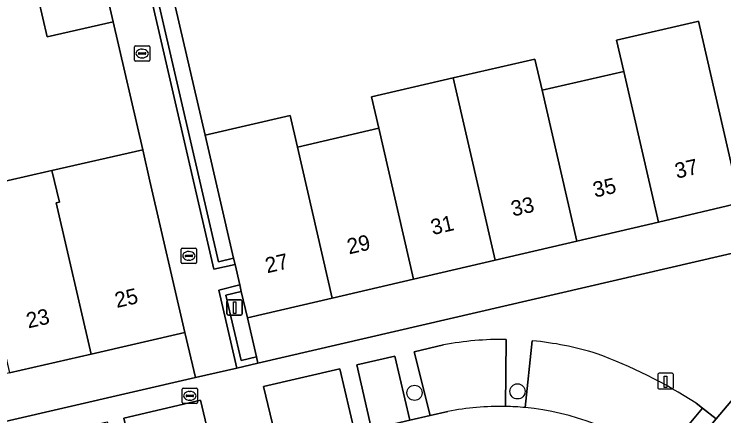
# Model space of a CAD drawing. Extents: x 156412 to 157779, y 382335 to 383768.
# Drawn here: x 156818.92 to 156864.72, y 382584.85 to 382610.78 of the extents above; entities that cross this region are included whole.
import ezdxf

# ---------------------------------------------------------------- set-up
doc = ezdxf.new("R2010")
doc.units = 0
for name, color, linetype in [('IMGEO_Boom', 7, 'Continuous'), ('IMGEO_Brandkraan', 7, 'Continuous'), ('IMGEO_Erf', 7, 'Continuous'), ('IMGEO_Groenvoorziening', 7, 'Continuous'), ('IMGEO_Kolk', 7, 'Continuous'), ('IMGEO_Laadpaal', 7, 'Continuous'), ('IMGEO_Lichtmast', 7, 'Continuous'), ('IMGEO_Muur', 7, 'Continuous'), ('IMGEO_Pand', 7, 'Continuous'), ('IMGEO_Pand_nummerreeks', 7, 'Continuous'), ('IMGEO_Parkeervlak_open', 7, 'Continuous'), ('IMGEO_Rijbaan_lokaal_open', 7, 'Continuous'), ('IMGEO_Voetpad_open', 7, 'Continuous')]:
    doc.layers.add(name, color=color, linetype=linetype)

msp = doc.modelspace()

# ---------------------------------------------------------------- linework, layer by layer
at = {"layer": 'IMGEO_Boom'}
for centre in [(156844.759, 382586.335), (156851.401, 382586.427)]:
    msp.add_circle(centre, 0.489, dxfattribs=at)
at = {"layer": 'IMGEO_Brandkraan'}
for p, q in [((156829.756, 382585.715), (156829.756, 382586.567)), ((156829.831, 382586.641), (156830.683, 382586.641)), ((156830.757, 382586.567), (156830.757, 382585.715)), ((156830.015, 382586.135), (156830.015, 382586.147)), ((156830.453, 382586.098), (156830.055, 382586.098)), ((156830.058, 382586.184), (156830.456, 382586.184)), ((156830.244, 382586.421), (156830.269, 382586.421)), ((156830.499, 382586.147), (156830.499, 382586.135)), ((156830.683, 382585.641), (156829.831, 382585.641)), ((156830.267, 382585.861), (156830.242, 382585.861))]:
    msp.add_line(p, q, dxfattribs=at)
for points in [[(156829.756, 382585.715), (156829.756, 382586.567)], [(156829.831, 382586.641), (156830.683, 382586.641)], [(156830.757, 382586.567), (156830.757, 382585.715)], [(156830.683, 382585.641), (156829.831, 382585.641)]]:
    msp.add_lwpolyline(points, dxfattribs=at)
for centre, radius, start, end in [((156829.833, 382586.565), 0.0765, 91.552, 178.448), ((156829.833, 382586.565), 0.0765, 91.552, 178.448), ((156830.681, 382586.565), 0.0765, 1.552, 88.448), ((156830.681, 382586.565), 0.0765, 1.552, 88.448), ((156830.055, 382586.144), 0.0403, 85.8775, 175.7526), ((156830.052, 382586.134), 0.0366, 178.938, 274.7102), ((156830.456, 382586.141), 0.043, 264.8664, 352.4533), ((156830.46, 382586.146), 0.0386, 1.7309, 96.639), ((156829.833, 382585.717), 0.0765, 181.552, 268.448), ((156829.833, 382585.717), 0.0765, 181.552, 268.448), ((156830.681, 382585.717), 0.0765, 271.552, 358.448), ((156830.681, 382585.717), 0.0765, 271.552, 358.448)]:
    msp.add_arc(centre, radius, start, end, dxfattribs=at)
for centre, major_axis, ratio, start_param, end_param in [((156830.243, 382586.141), (-0.387, 0.002), 0.722429, 4.712389, 7.853982), ((156830.268, 382586.141), (-0.39, 0.002), 0.717154, 1.570796, 4.712389)]:
    msp.add_ellipse(centre, major_axis=major_axis, ratio=ratio, start_param=start_param, end_param=end_param, dxfattribs=at)
at = {"layer": 'IMGEO_Erf'}
for points in [[(156777.894, 382590.654), (156783.154, 382591.87), (156788.417, 382593.085), (156794.262, 382594.436), (156800.108, 382595.787), (156805.37, 382597.003), (156810.631, 382598.218), (156815.892, 382599.434), (156821.154, 382600.649), (156821.36, 382600.697), (156827.213, 382602.013), (156825.3, 382610.293), (156821.059, 382609.319), (156820.499, 382611.756)], [(156829.34, 382611.218), (156831.242, 382602.959), (156836.734, 382604.23), (156837.2, 382602.203), (156842.451, 382603.42), (156841.986, 382605.445), (156847.247, 382606.663), (156852.527, 382607.885), (156852.992, 382605.864), (156858.262, 382607.085), (156857.798, 382609.104), (156863.022, 382610.313), (156863.078, 382610.326), (156865.776, 382598.593), (156860.497, 382597.361), (156855.229, 382596.131), (156849.951, 382594.899), (156844.692, 382593.671), (156839.443, 382592.446), (156833.97, 382591.169), (156834.559, 382588.649), (156834.65, 382588.258), (156868.154, 382596.018)]]:
    msp.add_lwpolyline(points, dxfattribs=at)
msp.add_lwpolyline([(156830.614, 382587.326), (156829.943, 382590.238), (156823.882, 382588.838), (156818.621, 382587.623), (156813.403, 382586.418), (156808.098, 382585.193), (156802.836, 382583.978), (156796.99, 382582.627), (156791.144, 382581.277), (156785.883, 382580.062), (156780.621, 382578.847), (156775.36, 382577.632), (156770.098, 382576.416), (156764.837, 382575.201), (156759.384, 382573.942), (156760.061, 382571.022)], close=True, dxfattribs=at)
at = {"layer": 'IMGEO_Groenvoorziening'}
for points in [[(156829.34, 382611.218), (156828.87, 382613.267), (156827.892, 382613.043), (156832.104, 382594.787), (156833.079, 382595.021), (156831.242, 382602.959)], [(156833.561, 382588.417), (156834.559, 382588.649), (156833.97, 382591.169), (156833.573, 382592.883), (156832.585, 382592.65)]]:
    msp.add_lwpolyline(points, close=True, dxfattribs=at)
at = {"layer": 'IMGEO_Kolk'}
for p, q in [((156826.678, 382607.815), (156826.678, 382608.667)), ((156826.753, 382608.741), (156827.605, 382608.741)), ((156827.679, 382608.667), (156827.679, 382607.815)), ((156826.937, 382608.235), (156826.937, 382608.247)), ((156827.375, 382608.198), (156826.977, 382608.198)), ((156826.98, 382608.284), (156827.378, 382608.284)), ((156827.166, 382608.521), (156827.191, 382608.521)), ((156827.421, 382608.247), (156827.421, 382608.235)), ((156827.605, 382607.741), (156826.753, 382607.741)), ((156827.189, 382607.961), (156827.164, 382607.961)), ((156829.694, 382594.752), (156829.694, 382595.604)), ((156829.769, 382595.678), (156830.621, 382595.678)), ((156830.182, 382595.458), (156830.207, 382595.458)), ((156830.695, 382595.604), (156830.695, 382594.752)), ((156829.953, 382595.172), (156829.953, 382595.184)), ((156830.391, 382595.135), (156829.993, 382595.135)), ((156829.996, 382595.221), (156830.394, 382595.221)), ((156830.205, 382594.898), (156830.18, 382594.898)), ((156830.437, 382595.184), (156830.437, 382595.172)), ((156830.621, 382594.678), (156829.769, 382594.678))]:
    msp.add_line(p, q, dxfattribs=at)
for points in [[(156826.678, 382607.815), (156826.678, 382608.667)], [(156826.753, 382608.741), (156827.605, 382608.741)], [(156827.679, 382608.667), (156827.679, 382607.815)], [(156827.605, 382607.741), (156826.753, 382607.741)], [(156829.694, 382594.752), (156829.694, 382595.604)], [(156829.769, 382595.678), (156830.621, 382595.678)], [(156830.695, 382595.604), (156830.695, 382594.752)], [(156830.621, 382594.678), (156829.769, 382594.678)]]:
    msp.add_lwpolyline(points, dxfattribs=at)
for centre, radius, start, end in [((156826.755, 382608.665), 0.0765, 91.552, 178.448), ((156826.755, 382608.665), 0.0765, 91.552, 178.448), ((156827.603, 382608.665), 0.0765, 1.552, 88.448), ((156827.603, 382608.665), 0.0765, 1.552, 88.448), ((156826.977, 382608.244), 0.0403, 85.8775, 175.7526), ((156826.974, 382608.234), 0.0366, 178.938, 274.7102), ((156827.378, 382608.241), 0.043, 264.8664, 352.4533), ((156827.382, 382608.246), 0.0386, 1.7309, 96.639), ((156826.755, 382607.817), 0.0765, 181.552, 268.448), ((156826.755, 382607.817), 0.0765, 181.552, 268.448), ((156827.603, 382607.817), 0.0765, 271.552, 358.448), ((156827.603, 382607.817), 0.0765, 271.552, 358.448), ((156829.771, 382595.602), 0.0765, 91.552, 178.448), ((156829.771, 382595.602), 0.0765, 91.552, 178.448), ((156830.619, 382595.602), 0.0765, 1.552, 88.448), ((156830.619, 382595.602), 0.0765, 1.552, 88.448), ((156829.993, 382595.181), 0.0403, 85.8775, 175.7526), ((156829.99, 382595.171), 0.0366, 178.938, 274.7102), ((156830.394, 382595.178), 0.043, 264.8664, 352.4533), ((156830.398, 382595.183), 0.0386, 1.7309, 96.639), ((156829.771, 382594.754), 0.0765, 181.552, 268.448), ((156829.771, 382594.754), 0.0765, 181.552, 268.448), ((156830.619, 382594.754), 0.0765, 271.552, 358.448), ((156830.619, 382594.754), 0.0765, 271.552, 358.448)]:
    msp.add_arc(centre, radius, start, end, dxfattribs=at)
for centre, major_axis, ratio, start_param, end_param in [((156827.165, 382608.241), (-0.387, 0.002), 0.722429, 4.712389, 7.853982), ((156827.19, 382608.241), (-0.39, 0.002), 0.717154, 1.570796, 4.712389), ((156830.181, 382595.178), (-0.387, 0.002), 0.722429, 4.712389, 7.853982), ((156830.206, 382595.178), (-0.39, 0.002), 0.717154, 1.570796, 4.712389)]:
    msp.add_ellipse(centre, major_axis=major_axis, ratio=ratio, start_param=start_param, end_param=end_param, dxfattribs=at)
at = {"layer": 'IMGEO_Laadpaal'}
for p, q in [((156860.461, 382587.51), (156860.461, 382586.669)), ((156860.461, 382587.51), (156860.461, 382586.669)), ((156861.377, 382587.594), (156860.536, 382587.594)), ((156861.377, 382587.594), (156860.536, 382587.594)), ((156861.461, 382586.678), (156861.461, 382587.519)), ((156861.461, 382586.678), (156861.461, 382587.519)), ((156860.545, 382586.594), (156861.386, 382586.594)), ((156860.545, 382586.594), (156861.386, 382586.594))]:
    msp.add_line(p, q, dxfattribs=at)
msp.add_lwpolyline([(156860.876, 382587.407), (156861.036, 382587.407), (156861.036, 382586.674), (156860.876, 382586.674), (156860.876, 382587.407)], dxfattribs=at)
for centre, start, end in [((156860.539, 382587.516), 92.4484, 184.2845), ((156860.539, 382587.516), 92.4484, 184.2845), ((156861.383, 382587.516), 2.4484, 94.2845), ((156861.383, 382587.516), 2.4484, 94.2845), ((156860.539, 382586.672), 182.4484, 274.2845), ((156860.539, 382586.672), 182.4484, 274.2845), ((156861.383, 382586.672), 272.4484, 4.2845), ((156861.383, 382586.672), 272.4484, 4.2845)]:
    msp.add_arc(centre, 0.0779, start, end, dxfattribs=at)
at = {"layer": 'IMGEO_Lichtmast'}
for p, q in [((156832.651, 382591.438), (156832.651, 382592.238)), ((156832.651, 382592.238), (156832.651, 382591.438)), ((156832.751, 382592.338), (156833.541, 382592.338)), ((156833.541, 382592.338), (156832.751, 382592.338)), ((156833.641, 382592.238), (156833.641, 382591.438)), ((156833.641, 382591.438), (156833.641, 382592.238)), ((156833.541, 382591.338), (156832.751, 382591.338)), ((156832.751, 382591.338), (156833.541, 382591.338))]:
    msp.add_line(p, q, dxfattribs=at)
msp.add_lwpolyline([(156833.071, 382592.213), (156833.221, 382592.213), (156833.221, 382591.463), (156833.071, 382591.463), (156833.071, 382592.213)], dxfattribs=at)
for centre, start, end in [((156832.751, 382592.238), 90, 180), ((156832.751, 382592.238), 90, 180), ((156833.541, 382592.238), 0, 90), ((156833.541, 382592.238), 360, 90), ((156832.751, 382591.438), 180, 270), ((156832.751, 382591.438), 180, 270), ((156833.541, 382591.438), 270, 0), ((156833.541, 382591.438), 270, 0)]:
    msp.add_arc(centre, 0.1, start, end, dxfattribs=at)
at = {"layer": 'IMGEO_Muur'}
for points in [[(156827.892, 382613.043), (156828.87, 382613.267), (156828.778, 382613.665), (156827.414, 382613.34), (156831.805, 382594.319), (156833.171, 382594.621), (156833.079, 382595.021), (156832.104, 382594.787)], [(156832.585, 382592.65), (156833.573, 382592.883), (156833.478, 382593.297), (156832.121, 382592.971), (156833.281, 382587.934), (156834.65, 382588.258), (156834.559, 382588.649), (156833.561, 382588.417)]]:
    msp.add_lwpolyline(points, close=True, dxfattribs=at)
for points in [[(156831.242, 382602.959), (156829.34, 382611.218)], [(156825.3, 382610.293), (156827.681, 382599.996)]]:
    msp.add_lwpolyline(points, dxfattribs=at)
at = {"layer": 'IMGEO_Pand'}
for points in [[(156824.748, 382612.732), (156820.499, 382611.756), (156821.059, 382609.319), (156825.3, 382610.293)], [(156863.078, 382610.326), (156863.022, 382610.313), (156857.798, 382609.104), (156858.262, 382607.085), (156860.497, 382597.361), (156865.776, 382598.593)], [(156852.992, 382605.864), (156852.527, 382607.885), (156847.247, 382606.663), (156849.951, 382594.899), (156855.229, 382596.131)], [(156858.262, 382607.085), (156852.992, 382605.864), (156855.229, 382596.131), (156860.497, 382597.361)], [(156847.247, 382606.663), (156841.986, 382605.445), (156842.451, 382603.42), (156844.692, 382593.671), (156849.951, 382594.899)], [(156837.2, 382602.203), (156836.734, 382604.23), (156831.242, 382602.959), (156833.079, 382595.021), (156833.171, 382594.621), (156833.478, 382593.297), (156833.573, 382592.883), (156833.97, 382591.169), (156839.443, 382592.446)], [(156842.451, 382603.42), (156837.2, 382602.203), (156839.443, 382592.446), (156844.692, 382593.671)], [(156827.681, 382599.996), (156827.213, 382602.013), (156821.36, 382600.697), (156821.836, 382598.641), (156821.629, 382598.593), (156823.882, 382588.838), (156829.943, 382590.238)], [(156815.892, 382599.434), (156818.621, 382587.623), (156823.882, 382588.838), (156821.629, 382598.593), (156821.836, 382598.641), (156821.36, 382600.697), (156821.154, 382600.649)]]:
    msp.add_lwpolyline(points, close=True, dxfattribs=at)
at = {"layer": 'IMGEO_Parkeervlak_open'}
for points in [[(156850.628, 382585.457), (156850.676, 382589.782)], [(156846.631, 382589.432), (156844.725, 382588.992), (156845.771, 382584.863), (156846.914, 382585.124)], [(156852.358, 382589.694), (156851.897, 382585.383)], [(156860.39, 382582.117), (156860.54, 382581.992), (156863.333, 382585.351), (156862.931, 382585.667)]]:
    msp.add_lwpolyline(points, dxfattribs=at)
for points in [[(156843.483, 382588.705), (156841.03, 382588.138), (156841.972, 382583.994), (156844.456, 382584.562)], [(156839.933, 382587.885), (156835.013, 382586.749), (156836.003, 382582.63), (156840.894, 382583.748)], [(156830.955, 382585.851), (156826.004, 382584.706), (156827.007, 382580.55), (156831.935, 382581.69)]]:
    msp.add_lwpolyline(points, close=True, dxfattribs=at)
for centre, radius, start, end in [((156850.437, 382568.996), 20.787, 89.3409, 100.5497), ((156850.433, 382569.094), 20.69, 73.0027, 84.6609), ((156845.009, 382557.769), 33.159, 57.2824, 69.7582), ((156850.275, 382568.517), 16.943, 88.8059, 101.4411), ((156850.273, 382568.485), 16.976, 53.4197, 84.5116)]:
    msp.add_arc(centre, radius, start, end, dxfattribs=at)
at = {"layer": 'IMGEO_Rijbaan_lokaal_open'}
msp.add_lwpolyline([(156846.914, 382585.124), (156845.771, 382584.863), (156844.456, 382584.562), (156841.972, 382583.994), (156840.894, 382583.748), (156836.003, 382582.63), (156831.935, 382581.69), (156827.007, 382580.55), (156825.98, 382580.312), (156821.066, 382579.175), (156820.053, 382578.941), (156815.056, 382577.785), (156814.008, 382577.542), (156804.335, 382575.304), (156802.952, 382574.984), (156800.441, 382574.403), (156799.271, 382574.133), (156791.99, 382572.448), (156790.817, 382572.176), (156785.914, 382571.042), (156784.743, 382570.771), (156782.406, 382570.23), (156781.292, 382569.972)], dxfattribs=at)
for centre, radius, start, end in [((156850.275, 382568.517), 16.943, 88.8059, 101.4411), ((156850.284, 382568.635), 16.825, 84.4978, 88.8275), ((156850.273, 382568.485), 16.976, 53.4197, 84.5116)]:
    msp.add_arc(centre, radius, start, end, dxfattribs=at)
at = {"layer": 'IMGEO_Voetpad_open'}
for points in [[(156933.244, 382662.842), (156934.51, 382664.323), (156932.879, 382665.646), (156931.633, 382664.111), (156871.455, 382593.202), (156864.221, 382584.653), (156861.376, 382581.295), (156860.948, 382580.803), (156862.534, 382579.499), (156863.708, 382580.895)], [(156862.931, 382585.667), (156863.333, 382585.351), (156864.221, 382584.653), (156871.455, 382593.202), (156868.154, 382596.018), (156834.65, 382588.258), (156833.281, 382587.934), (156830.614, 382587.326), (156760.061, 382571.022), (156760.417, 382569.534), (156761.414, 382569.765), (156766.161, 382570.863), (156767.11, 382566.691), (156769.209, 382567.177), (156768.23, 382571.341), (156780.307, 382574.135)], [(156850.676, 382589.782), (156850.628, 382585.457)], [(156814.058, 382581.942), (156819.046, 382583.096), (156820.053, 382578.941), (156821.066, 382579.175), (156820.039, 382583.326), (156824.912, 382584.453), (156825.98, 382580.312), (156827.007, 382580.55), (156826.004, 382584.706), (156830.955, 382585.851), (156831.935, 382581.69), (156836.003, 382582.63), (156835.013, 382586.749), (156839.933, 382587.885), (156840.894, 382583.748), (156841.972, 382583.994), (156841.03, 382588.138), (156843.483, 382588.705), (156844.456, 382584.562), (156845.771, 382584.863), (156844.725, 382588.992), (156846.631, 382589.432)], [(156851.897, 382585.383), (156852.358, 382589.694)]]:
    msp.add_lwpolyline(points, dxfattribs=at)
for points in [[(156820.465, 382643.445), (156817.808, 382642.832), (156818.475, 382639.91), (156821.401, 382627.236), (156823.777, 382616.925), (156824.341, 382614.493), (156824.748, 382612.732), (156825.3, 382610.293), (156827.213, 382602.013), (156827.681, 382599.996), (156829.943, 382590.238), (156830.614, 382587.326), (156833.281, 382587.934), (156832.121, 382592.971), (156833.478, 382593.297), (156833.171, 382594.621), (156831.805, 382594.319), (156827.414, 382613.34), (156828.778, 382613.665), (156828.384, 382615.409), (156827.008, 382615.111)], [(156864.221, 382584.653), (156863.333, 382585.351), (156860.54, 382581.992), (156861.376, 382581.295)]]:
    msp.add_lwpolyline(points, close=True, dxfattribs=at)
for centre, radius, start, end in [((156850.437, 382568.996), 20.787, 89.3409, 100.5497), ((156850.433, 382569.094), 20.69, 73.0027, 84.6609), ((156845.009, 382557.769), 33.159, 57.2824, 69.7582), ((156850.284, 382568.635), 16.825, 84.4978, 88.8275)]:
    msp.add_arc(centre, radius, start, end, dxfattribs=at)

# ---------------------------------------------------------------- texts
at = {"layer": 'IMGEO_Pand_nummerreeks'}
for s, rotation, p in [('37', 13.0004, (156861.684, 382600.154)), ('35', 13.0004, (156856.396, 382598.933)), ('33', 13.0004, (156851.109, 382597.712)), ('31', 13.0004, (156845.928, 382596.516)), ('29', 13.0004, (156840.53, 382595.269)), ('27', 13.0004, (156835.245, 382594.049)), ('25', 12.9718, (156825.539, 382591.808)), ('23', 13.0077, (156819.829, 382590.49))]:
    msp.add_text(s, height=1, rotation=rotation, dxfattribs=at).set_placement(p)

doc.saveas('drawing.dxf')
